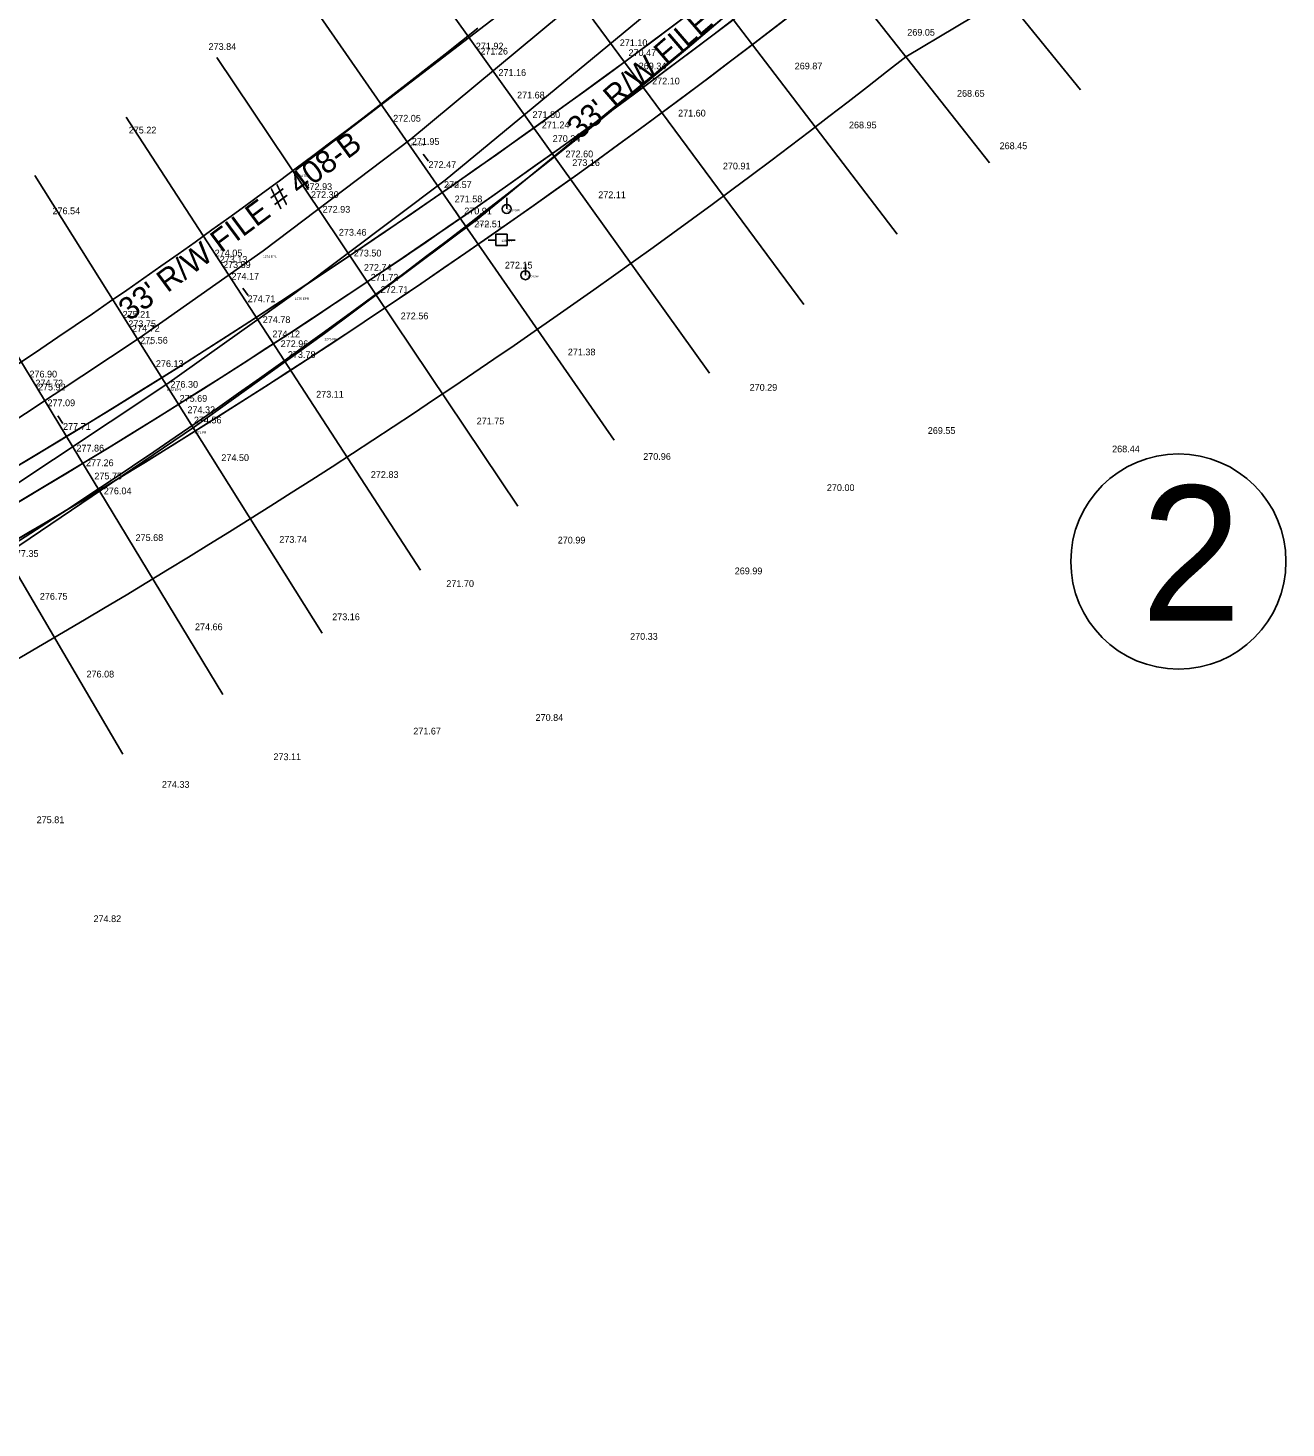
# Model space of a CAD drawing. Extents: x 49683 to 58852, y 49525 to 54803.
# Drawn here: x 52213 to 52772, y 49993 to 50615 of the extents above; entities that cross this region are included whole.
import ezdxf

# ---------------------------------------------------------------- set-up
doc = ezdxf.new("R2010")
doc.units = 0
for name, color, linetype in [('Level 1', 7, 'Continuous'), ('Level 11', 7, 'Continuous'), ('Level 13', 7, 'Continuous'), ('Level 19', 7, 'Continuous'), ('Level 20', 7, 'Continuous'), ('Level 25', 7, 'Continuous'), ('Level 29', 7, 'Continuous'), ('Level 3', 7, 'Continuous'), ('Level 32', 7, 'Continuous'), ('Level 33', 7, 'Continuous'), ('Level 50', 7, 'Continuous'), ('Level 53', 7, 'Continuous'), ('Level 58', 7, 'Continuous'), ('Level 59', 7, 'Continuous'), ('Level 61', 7, 'Continuous'), ('Level 63', 7, 'Continuous'), ('Level 8', 7, 'Continuous'), ('Level 9', 7, 'Continuous')]:
    doc.layers.add(name, color=color, linetype=linetype)

# ---------------------------------------------------------------- blocks, each defined once
blk = doc.blocks.new('GW')
at = {"layer": 'Level 9'}
blk.add_line((0, 0), (0, 5), dxfattribs=at)
blk.add_circle((0, 0), 2, dxfattribs=at)
blk = doc.blocks.new('PP')
at = {"layer": 'Level 9'}
for p, q in [((2.53, 2.45), (-2.47, 2.45)), ((-2.47, 2.45), (-2.47, -2.55)), ((2.53, -2.55), (2.53, 2.45)), ((-5.91, -0.11), (-2.44, -0.11)), ((-2.47, -2.55), (2.53, -2.55)), ((2.45, -0.11), (6.09, -0.11))]:
    blk.add_line(p, q, dxfattribs=at)

msp = doc.modelspace()

# ---------------------------------------------------------------- linework, layer by layer
at = {"layer": 'Level 1'}
for p, q in [((52390.95, 50555.86), (52388.5, 50559.03)), ((52310.71, 50496.19), (52308.38, 50499.44)), ((52228.44, 50439.35), (52226.22, 50442.68))]:
    msp.add_line(p, q, dxfattribs=at)
at = {"layer": 'Level 11'}
msp.add_line((52331.92, 50551.79), (52527.71, 50702.05), dxfattribs=at)
at = {"layer": 'Level 13'}
for radius, start, end in [(2897.79, 282.71776, 311.63339), (2831.79, 296.71776, 308.71775)]:
    msp.add_arc((50641.55, 52824.48), radius, start, end, dxfattribs=at)
at = {"layer": 'Level 19'}
for p, q in [((52486.3, 50588.68), (52483.92, 50591.9)), ((52405.02, 50530.44), (52402.74, 50533.73)), ((52321.99, 50474.71), (52319.81, 50478.07)), ((52237.3, 50421.55), (52235.23, 50424.97))]:
    msp.add_line(p, q, dxfattribs=at)
msp.add_arc((50539, 53220.69), 3274.06, 284.51284, 311.63337, dxfattribs=at)
at = {"layer": 'Level 20'}
for radius in [3260.06, 3288.06]:
    msp.add_arc((50539, 53220.69), radius, 284.51284, 311.63318, dxfattribs=at)
at = {"layer": 'Level 25'}
msp.add_circle((52724.02, 50377.96), 47.8, dxfattribs=at)
at = {"layer": 'Level 29'}
for p, q in [((52486.3, 50588.68), (52483.92, 50591.9)), ((52405.02, 50530.44), (52402.74, 50533.73)), ((52321.99, 50474.71), (52319.81, 50478.07)), ((52237.3, 50421.55), (52235.23, 50424.97))]:
    msp.add_line(p, q, dxfattribs=at)
msp.add_arc((50539, 53220.69), 3274.06, 284.51246, 311.63337, dxfattribs=at)
at = {"layer": 'Level 3'}
for p, q in [((52383.07, 50565.65), (52536.19, 50693.05)), ((52398.28, 50547.35), (52535.34, 50660.73)), ((52317.4, 50515.97), (52383.07, 50565.65)), ((52331.52, 50497.22), (52398.28, 50547.35)), ((52262.41, 50477.27), (52317.4, 50515.97)), ((52274.71, 50456.75), (52331.52, 50497.22)), ((52176.97, 50420.76), (52262.41, 50477.27)), ((52192.62, 50402.34), (52274.71, 50456.75))]:
    msp.add_line(p, q, dxfattribs=at)
at = {"layer": 'Level 33'}
msp.add_line((52602.91, 50602.26), (52691.55, 50655.02), dxfattribs=at)
msp.add_arc((50539, 53220.69), 3334.06, 284.51246, 308.24612, dxfattribs=at)
at = {"layer": 'Level 50'}
for p, q in [((52529.09, 50773.73), (52680.52, 50587.53)), ((52491.49, 50743.62), (52640.06, 50555.14)), ((52453.43, 50714.1), (52599.11, 50523.36)), ((52414.93, 50685.15), (52557.67, 50492.22)), ((52375.99, 50656.8), (52515.77, 50461.71)), ((52336.62, 50629.05), (52473.41, 50431.84)), ((52296.84, 50601.9), (52430.6, 50402.63)), ((52256.64, 50575.36), (52387.34, 50374.07)), ((52216.04, 50549.44), (52343.65, 50346.18)), ((52175.06, 50524.14), (52299.55, 50318.95)), ((52133.69, 50499.47), (52255.03, 50292.4))]:
    msp.add_line(p, q, dxfattribs=at)
at = {"layer": 'Level 63'}
for radius in [3260.06, 3274.06, 3274.06, 3288.06]:
    msp.add_arc((50539, 53220.69), radius, 284.51284, 311.07341, dxfattribs=at)
at = {"layer": 'Level 8'}
for p, q in [((52412.59, 50530.13), (52537.26, 50632.33)), ((52344.69, 50479.28), (52412.59, 50530.13)), ((52286.9, 50437.81), (52344.69, 50479.28)), ((52204.78, 50382.12), (52286.9, 50437.81))]:
    msp.add_line(p, q, dxfattribs=at)

# ---------------------------------------------------------------- block references
at = {"layer": 'Level 9'}
for name, p in [('GW', (52425.65, 50534.62)), ('PP', (52423.29, 50520.92)), ('GW', (52433.95, 50505.2))]:
    msp.add_blockref(name, p, dxfattribs=at)

# ---------------------------------------------------------------- texts
at = {"layer": 'Level 25'}
for rotation, p in [(40.72213, (52457.9, 50565.13)), (36.5988, (52257.95, 50484.53))]:
    msp.add_text("33' R/W FILE # 408-B", height=10, rotation=rotation, dxfattribs=at).set_placement(p)
msp.add_text('2', height=60, dxfattribs=at).set_placement((52707.42, 50351.68))
at = {"layer": 'Level 32'}
for s, p in [('269.05', (52603.58, 50611.6)), ('273.84', (52293.19, 50605.27)), ('271.92', (52411.91, 50605.47)), ('271.26', (52413.91, 50603.24)), ('271.10', (52475.85, 50606.95)), ('270.47', (52479.73, 50602.53)), ('271.16', (52421.96, 50593.73)), ('269.34', (52484.27, 50596.63)), ('269.87', (52553.57, 50596.62)), ('272.10', (52490.23, 50589.95)), ('271.68', (52430.23, 50583.71)), ('268.65', (52625.67, 50584.45)), ('272.05', (52375.21, 50573.42)), ('271.80', (52437.09, 50575.02)), ('271.60', (52501.76, 50575.69)), ('275.22', (52257.72, 50568.16)), ('271.24', (52441.24, 50570.47)), ('268.95', (52577.68, 50570.41)), ('271.95', (52383.47, 50563.1)), ('270.24', (52446.06, 50564.4)), ('268.45', (52644.6, 50561.18)), ('272.60', (52451.76, 50557.57)), ('273.16', (52454.76, 50553.69)), ('272.47', (52390.91, 50552.84)), ('270.91', (52521.66, 50552.18)), ('272.93', (52335.8, 50543.02)), ('272.57', (52397.79, 50543.91)), ('272.30', (52338.7, 50539.48)), ('271.58', (52402.51, 50537.56)), ('272.11', (52466.3, 50539.41)), ('276.54', (52223.85, 50532.28)), ('272.93', (52343.85, 50532.97)), ('270.91', (52406.77, 50532.22)), ('273.46', (52351.07, 50522.76)), ('272.51', (52411.2, 50526.45)), ('274.05', (52295.91, 50513.54)), ('273.13', (52298.14, 50510.74)), ('273.50', (52357.69, 50513.5)), ('273.59', (52299.61, 50508.36)), ('272.74', (52362.18, 50507.13)), ('272.15', (52424.82, 50508.14)), ('274.17', (52303.35, 50503.21)), ('271.72', (52365.23, 50502.77)), ('274.71', (52310.55, 50493.2)), ('272.71', (52369.65, 50497.31)), ('275.21', (52255, 50486.28)), ('272.56', (52378.54, 50485.6)), ('273.75', (52257.52, 50482.11)), ('274.72', (52259.18, 50480.09)), ('274.78', (52317.26, 50483.94)), ('275.56', (52262.78, 50474.79)), ('274.12', (52321.53, 50477.6)), ('272.96', (52325.22, 50473.23)), ('273.78', (52328.41, 50468.42)), ('271.38', (52452.79, 50469.57)), ('276.13', (52269.78, 50464.4)), ('276.90', (52213.61, 50459.74)), ('274.72', (52216.26, 50455.76)), ('275.92', (52217.39, 50453.98)), ('276.30', (52276.23, 50455.19)), ('270.29', (52533.54, 50453.84)), ('275.69', (52280.31, 50448.96)), ('273.11', (52340.99, 50450.8)), ('277.09', (52221.62, 50446.98)), ('274.32', (52283.81, 50443.89)), ('277.71', (52228.54, 50436.46)), ('274.56', (52286.67, 50439.33)), ('271.75', (52412.29, 50438.9)), ('269.55', (52612.69, 50434.68)), ('277.86', (52234.49, 50426.85)), ('270.96', (52486.27, 50423.14)), ('268.44', (52694.58, 50426.49)), ('277.26', (52238.73, 50420.34)), ('274.50', (52298.87, 50422.62)), ('275.75', (52242.45, 50414.45)), ('272.83', (52365.27, 50415.12)), ('276.04', (52246.66, 50407.86)), ('270.00', (52567.86, 50409.31)), ('275.68', (52260.75, 50387.1)), ('273.74', (52324.61, 50386.29)), ('270.99', (52448.3, 50385.98)), ('277.35', (52205.36, 50380.03)), ('269.99', (52526.93, 50372.31)), ('276.75', (52218.23, 50361.01)), ('271.70', (52398.82, 50366.67)), ('273.16', (52348.11, 50351.91)), ('274.66', (52287.14, 50347.46)), ('270.33', (52480.45, 50343.2)), ('276.08', (52238.96, 50326.46)), ('270.84', (52438.46, 50307.17)), ('271.67', (52384.12, 50301.13)), ('273.11', (52322.01, 50289.73)), ('274.33', (52272.43, 50277.44)), ('275.81', (52216.81, 50261.73)), ('274.82', (52242.08, 50217.78))]:
    msp.add_text(s, height=3, dxfattribs=at).set_placement(p)
at = {"layer": 'Level 53'}
for s, p in [('1285 EPL', (52383.07, 50562.65)), ('1286 EPR', (52398.28, 50544.36)), ('1274 EPL', (52317.4, 50512.97)), ('1275 EPR', (52331.52, 50494.22)), ('1273 EPL', (52262.41, 50474.27)), ('1272 EPR', (52274.71, 50453.75))]:
    msp.add_text(s, height=1, dxfattribs=at).set_placement(p)
at = {"layer": 'Level 58'}
for s, p in [('1287 FR', (52412.59, 50527.13)), ('1276 FR', (52344.69, 50476.28)), ('1271 FR', (52286.9, 50434.81))]:
    msp.add_text(s, height=1, dxfattribs=at).set_placement(p)
at = {"layer": 'Level 59'}
for s, p in [('1288 GW', (52425.65, 50533.62)), ('1289 PP', (52423.29, 50519.92)), ('1290 GW', (52433.95, 50504.2))]:
    msp.add_text(s, height=1, dxfattribs=at).set_placement(p)
at = {"layer": 'Level 61'}
msp.add_text('1284 TLA', height=1, dxfattribs=at).set_placement((52331.92, 50548.79))

doc.saveas('drawing.dxf')
